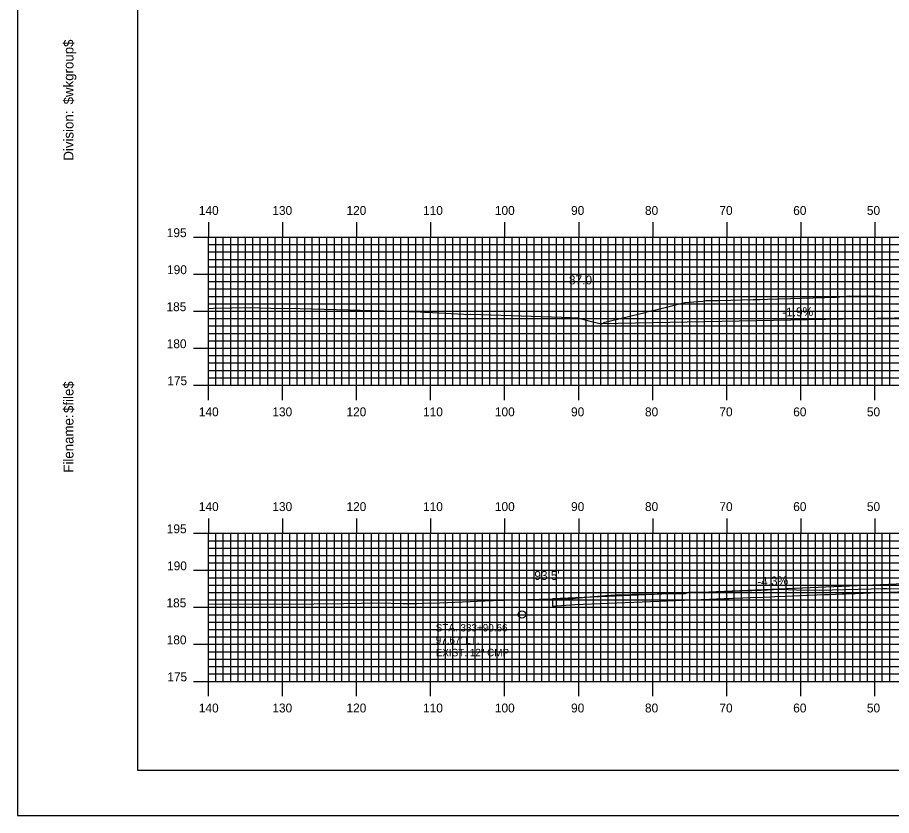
# Model space of a CAD drawing. Extents: x 1823179 to 1823522, y 442591 to 442811.
# Drawn here: x 1823179 to 1823297, y 442590.5 to 442698.3 of the extents above; entities that cross this region are included whole.
import ezdxf

# ---------------------------------------------------------------- set-up
doc = ezdxf.new("R2010")
doc.units = 0
for name, color, linetype in [('ANNOTATION', 7, 'Continuous'), ('BORDER', 7, 'Continuous'), ('D_Drainage_Culvert', 7, 'Continuous'), ('D_Roadway_Drive_SubGrade', 7, 'Continuous'), ('D_Roadway_FinishedGrade', 7, 'Continuous'), ('D_Text_Monospaced', 7, 'Continuous'), ('D_Text_Standard', 7, 'Continuous'), ('H_V ANNOTATION', 7, 'Continuous'), ('MAJOR', 7, 'Continuous'), ('MINOR', 7, 'Continuous'), ('PLOT BOUNDARY', 7, 'Continuous'), ('S_Roadway_Centerline', 7, 'Continuous')]:
    doc.layers.add(name, color=color, linetype=linetype)

msp = doc.modelspace()

# ---------------------------------------------------------------- linework, layer by layer
at = {"layer": 'ANNOTATION'}
msp.add_line((1823310.91, 442622.37), (1823251.26, 442619.82), dxfattribs=at)
at = {"layer": 'BORDER'}
msp.add_lwpolyline([(1823195.2, 442596.67), (1823515.2, 442596.67), (1823515.2, 442806.67), (1823195.2, 442806.67)], close=True, dxfattribs=at)
at = {"layer": 'D_Drainage_Culvert'}
msp.add_circle((1823247.14, 442617.69), 0.5, dxfattribs=at)
at = {"layer": 'D_Roadway_Drive_SubGrade'}
msp.add_line((1823251.26, 442619.82), (1823251.26, 442618.81), dxfattribs=at)
msp.add_lwpolyline([(1823251.26, 442618.81), (1823254.29, 442619.05), (1823272.47, 442619.77), (1823274.43, 442619.84), (1823275.07, 442619.87), (1823275.67, 442619.89), (1823276.97, 442619.94), (1823278, 442619.98), (1823279.69, 442620.05), (1823280.76, 442620.09), (1823281.27, 442620.11), (1823282.72, 442620.17), (1823285.62, 442620.29), (1823285.82, 442620.29), (1823287.99, 442620.38), (1823288.64, 442620.41), (1823290.43, 442620.48), (1823290.86, 442620.49), (1823291.95, 442620.54), (1823292.18, 442620.55), (1823295.24, 442620.67), (1823295.7, 442620.69), (1823295.87, 442620.69), (1823295.89, 442620.69), (1823298.93, 442620.81)], dxfattribs=at)
at = {"layer": 'D_Roadway_FinishedGrade'}
msp.add_line((1823310.62, 442657.95), (1823257.79, 442656.97), dxfattribs=at)
at = {"layer": 'MAJOR'}
for p, q in [((1823204.8, 442670.67), (1823204.8, 442668.67)), ((1823214.8, 442670.67), (1823214.8, 442668.67)), ((1823224.8, 442670.67), (1823224.8, 442668.67)), ((1823234.8, 442670.67), (1823234.8, 442668.67)), ((1823244.8, 442670.67), (1823244.8, 442668.67)), ((1823254.8, 442670.67), (1823254.8, 442668.67)), ((1823264.8, 442670.67), (1823264.8, 442668.67)), ((1823274.8, 442670.67), (1823274.8, 442668.67)), ((1823284.8, 442670.67), (1823284.8, 442668.67)), ((1823294.8, 442670.67), (1823294.8, 442668.67)), ((1823202.79, 442668.67), (1823204.8, 442668.67)), ((1823204.8, 442668.67), (1823484.8, 442668.67)), ((1823204.8, 442648.67), (1823204.8, 442668.67)), ((1823204.8, 442648.67), (1823204.8, 442668.67)), ((1823204.8, 442668.67), (1823484.8, 442668.67)), ((1823214.8, 442648.67), (1823214.8, 442668.67)), ((1823224.8, 442648.67), (1823224.8, 442668.67)), ((1823234.8, 442648.67), (1823234.8, 442668.67)), ((1823244.8, 442648.67), (1823244.8, 442668.67)), ((1823254.8, 442648.67), (1823254.8, 442668.67)), ((1823264.8, 442648.67), (1823264.8, 442668.67)), ((1823274.8, 442648.67), (1823274.8, 442668.67)), ((1823284.8, 442648.67), (1823284.8, 442668.67)), ((1823294.8, 442648.67), (1823294.8, 442668.67)), ((1823202.79, 442663.67), (1823204.8, 442663.67)), ((1823204.8, 442663.67), (1823484.8, 442663.67)), ((1823202.79, 442658.67), (1823204.8, 442658.67)), ((1823204.8, 442658.67), (1823484.8, 442658.67)), ((1823202.79, 442653.67), (1823204.8, 442653.67)), ((1823204.8, 442653.67), (1823484.8, 442653.67)), ((1823202.79, 442648.67), (1823204.8, 442648.67)), ((1823204.8, 442648.67), (1823484.8, 442648.67)), ((1823204.8, 442648.67), (1823484.8, 442648.67)), ((1823204.8, 442646.66), (1823204.8, 442648.67)), ((1823214.8, 442646.66), (1823214.8, 442648.67)), ((1823224.8, 442646.66), (1823224.8, 442648.67)), ((1823234.8, 442646.66), (1823234.8, 442648.67)), ((1823244.8, 442646.66), (1823244.8, 442648.67)), ((1823254.8, 442646.66), (1823254.8, 442648.67)), ((1823264.8, 442646.66), (1823264.8, 442648.67)), ((1823274.8, 442646.66), (1823274.8, 442648.67)), ((1823284.8, 442646.66), (1823284.8, 442648.67)), ((1823294.8, 442646.66), (1823294.8, 442648.67)), ((1823204.8, 442630.67), (1823204.8, 442628.67)), ((1823214.8, 442630.67), (1823214.8, 442628.67)), ((1823224.8, 442630.67), (1823224.8, 442628.67)), ((1823234.8, 442630.67), (1823234.8, 442628.67)), ((1823244.8, 442630.67), (1823244.8, 442628.67)), ((1823254.8, 442630.67), (1823254.8, 442628.67)), ((1823264.8, 442630.67), (1823264.8, 442628.67)), ((1823274.8, 442630.67), (1823274.8, 442628.67)), ((1823284.8, 442630.67), (1823284.8, 442628.67)), ((1823294.8, 442630.67), (1823294.8, 442628.67)), ((1823202.79, 442628.67), (1823204.8, 442628.67)), ((1823204.8, 442628.67), (1823484.8, 442628.67)), ((1823204.8, 442608.67), (1823204.8, 442628.67)), ((1823204.8, 442608.67), (1823204.8, 442628.67)), ((1823204.8, 442628.67), (1823484.8, 442628.67)), ((1823214.8, 442608.67), (1823214.8, 442628.67)), ((1823224.8, 442608.67), (1823224.8, 442628.67)), ((1823234.8, 442608.67), (1823234.8, 442628.67)), ((1823244.8, 442608.67), (1823244.8, 442628.67)), ((1823254.8, 442608.67), (1823254.8, 442628.67)), ((1823264.8, 442608.67), (1823264.8, 442628.67)), ((1823274.8, 442608.67), (1823274.8, 442628.67)), ((1823284.8, 442608.67), (1823284.8, 442628.67)), ((1823294.8, 442608.67), (1823294.8, 442628.67)), ((1823202.79, 442623.67), (1823204.8, 442623.67)), ((1823204.8, 442623.67), (1823484.8, 442623.67)), ((1823202.79, 442618.67), (1823204.8, 442618.67)), ((1823204.8, 442618.67), (1823484.8, 442618.67)), ((1823202.79, 442613.67), (1823204.8, 442613.67)), ((1823204.8, 442613.67), (1823484.8, 442613.67)), ((1823202.79, 442608.67), (1823204.8, 442608.67)), ((1823204.8, 442608.67), (1823484.8, 442608.67)), ((1823204.8, 442608.67), (1823484.8, 442608.67)), ((1823204.8, 442606.66), (1823204.8, 442608.67)), ((1823214.8, 442606.66), (1823214.8, 442608.67)), ((1823224.8, 442606.66), (1823224.8, 442608.67)), ((1823234.8, 442606.66), (1823234.8, 442608.67)), ((1823244.8, 442606.66), (1823244.8, 442608.67)), ((1823254.8, 442606.66), (1823254.8, 442608.67)), ((1823264.8, 442606.66), (1823264.8, 442608.67)), ((1823274.8, 442606.66), (1823274.8, 442608.67)), ((1823284.8, 442606.66), (1823284.8, 442608.67)), ((1823294.8, 442606.66), (1823294.8, 442608.67))]:
    msp.add_line(p, q, dxfattribs=at)
at = {"layer": 'MINOR'}
for p, q in [((1823205.8, 442648.67), (1823205.8, 442668.67)), ((1823206.8, 442648.67), (1823206.8, 442668.67)), ((1823207.8, 442648.67), (1823207.8, 442668.67)), ((1823208.8, 442648.67), (1823208.8, 442668.67)), ((1823209.8, 442648.67), (1823209.8, 442668.67)), ((1823210.8, 442648.67), (1823210.8, 442668.67)), ((1823211.8, 442648.67), (1823211.8, 442668.67)), ((1823212.8, 442648.67), (1823212.8, 442668.67)), ((1823213.8, 442648.67), (1823213.8, 442668.67)), ((1823215.8, 442648.67), (1823215.8, 442668.67)), ((1823216.8, 442648.67), (1823216.8, 442668.67)), ((1823217.8, 442648.67), (1823217.8, 442668.67)), ((1823218.8, 442648.67), (1823218.8, 442668.67)), ((1823219.8, 442648.67), (1823219.8, 442668.67)), ((1823220.8, 442648.67), (1823220.8, 442668.67)), ((1823221.8, 442648.67), (1823221.8, 442668.67)), ((1823222.8, 442648.67), (1823222.8, 442668.67)), ((1823223.8, 442648.67), (1823223.8, 442668.67)), ((1823225.8, 442648.67), (1823225.8, 442668.67)), ((1823226.8, 442648.67), (1823226.8, 442668.67)), ((1823227.8, 442648.67), (1823227.8, 442668.67)), ((1823228.8, 442648.67), (1823228.8, 442668.67)), ((1823229.8, 442648.67), (1823229.8, 442668.67)), ((1823230.8, 442648.67), (1823230.8, 442668.67)), ((1823231.8, 442648.67), (1823231.8, 442668.67)), ((1823232.8, 442648.67), (1823232.8, 442668.67)), ((1823233.8, 442648.67), (1823233.8, 442668.67)), ((1823235.8, 442648.67), (1823235.8, 442668.67)), ((1823236.8, 442648.67), (1823236.8, 442668.67)), ((1823237.8, 442648.67), (1823237.8, 442668.67)), ((1823238.8, 442648.67), (1823238.8, 442668.67)), ((1823239.8, 442648.67), (1823239.8, 442668.67)), ((1823240.8, 442648.67), (1823240.8, 442668.67)), ((1823241.8, 442648.67), (1823241.8, 442668.67)), ((1823242.8, 442648.67), (1823242.8, 442668.67)), ((1823243.8, 442648.67), (1823243.8, 442668.67)), ((1823245.8, 442648.67), (1823245.8, 442668.67)), ((1823246.8, 442648.67), (1823246.8, 442668.67)), ((1823247.8, 442648.67), (1823247.8, 442668.67)), ((1823248.8, 442648.67), (1823248.8, 442668.67)), ((1823249.8, 442648.67), (1823249.8, 442668.67)), ((1823250.8, 442648.67), (1823250.8, 442668.67)), ((1823251.8, 442648.67), (1823251.8, 442668.67)), ((1823252.8, 442648.67), (1823252.8, 442668.67)), ((1823253.8, 442648.67), (1823253.8, 442668.67)), ((1823255.8, 442648.67), (1823255.8, 442668.67)), ((1823256.8, 442648.67), (1823256.8, 442668.67)), ((1823257.8, 442648.67), (1823257.8, 442668.67)), ((1823258.8, 442648.67), (1823258.8, 442668.67)), ((1823259.8, 442648.67), (1823259.8, 442668.67)), ((1823260.8, 442648.67), (1823260.8, 442668.67)), ((1823261.8, 442648.67), (1823261.8, 442668.67)), ((1823262.8, 442648.67), (1823262.8, 442668.67)), ((1823263.8, 442648.67), (1823263.8, 442668.67)), ((1823265.8, 442648.67), (1823265.8, 442668.67)), ((1823266.8, 442648.67), (1823266.8, 442668.67)), ((1823267.8, 442648.67), (1823267.8, 442668.67)), ((1823268.8, 442648.67), (1823268.8, 442668.67)), ((1823269.8, 442648.67), (1823269.8, 442668.67)), ((1823270.8, 442648.67), (1823270.8, 442668.67)), ((1823271.8, 442648.67), (1823271.8, 442668.67)), ((1823272.8, 442648.67), (1823272.8, 442668.67)), ((1823273.8, 442648.67), (1823273.8, 442668.67)), ((1823275.8, 442648.67), (1823275.8, 442668.67)), ((1823276.8, 442648.67), (1823276.8, 442668.67)), ((1823277.8, 442648.67), (1823277.8, 442668.67)), ((1823278.8, 442648.67), (1823278.8, 442668.67)), ((1823279.8, 442648.67), (1823279.8, 442668.67)), ((1823280.8, 442648.67), (1823280.8, 442668.67)), ((1823281.8, 442648.67), (1823281.8, 442668.67)), ((1823282.8, 442648.67), (1823282.8, 442668.67)), ((1823283.8, 442648.67), (1823283.8, 442668.67)), ((1823285.8, 442648.67), (1823285.8, 442668.67)), ((1823286.8, 442648.67), (1823286.8, 442668.67)), ((1823287.8, 442648.67), (1823287.8, 442668.67)), ((1823288.8, 442648.67), (1823288.8, 442668.67)), ((1823289.8, 442648.67), (1823289.8, 442668.67)), ((1823290.8, 442648.67), (1823290.8, 442668.67)), ((1823291.8, 442648.67), (1823291.8, 442668.67)), ((1823292.8, 442648.67), (1823292.8, 442668.67)), ((1823293.8, 442648.67), (1823293.8, 442668.67)), ((1823295.8, 442648.67), (1823295.8, 442668.67)), ((1823296.8, 442648.67), (1823296.8, 442668.67)), ((1823204.8, 442667.67), (1823484.8, 442667.67)), ((1823204.8, 442667.67), (1823206.8, 442667.67)), ((1823204.8, 442666.67), (1823484.8, 442666.67)), ((1823204.8, 442666.67), (1823206.8, 442666.67)), ((1823204.8, 442665.67), (1823484.8, 442665.67)), ((1823204.8, 442665.67), (1823206.8, 442665.67)), ((1823204.8, 442664.67), (1823484.8, 442664.67)), ((1823204.8, 442664.67), (1823206.8, 442664.67)), ((1823204.8, 442662.67), (1823484.8, 442662.67)), ((1823204.8, 442662.67), (1823206.8, 442662.67)), ((1823204.8, 442661.67), (1823484.8, 442661.67)), ((1823204.8, 442661.67), (1823206.8, 442661.67)), ((1823204.8, 442660.67), (1823484.8, 442660.67)), ((1823204.8, 442660.67), (1823206.8, 442660.67)), ((1823204.8, 442659.67), (1823484.8, 442659.67)), ((1823204.8, 442659.67), (1823206.8, 442659.67)), ((1823204.8, 442657.67), (1823484.8, 442657.67)), ((1823204.8, 442657.67), (1823206.8, 442657.67)), ((1823204.8, 442656.67), (1823484.8, 442656.67)), ((1823204.8, 442656.67), (1823206.8, 442656.67)), ((1823204.8, 442655.67), (1823484.8, 442655.67)), ((1823204.8, 442655.67), (1823206.8, 442655.67)), ((1823204.8, 442654.67), (1823484.8, 442654.67)), ((1823204.8, 442654.67), (1823206.8, 442654.67)), ((1823204.8, 442652.67), (1823484.8, 442652.67)), ((1823204.8, 442652.67), (1823206.8, 442652.67)), ((1823204.8, 442651.67), (1823484.8, 442651.67)), ((1823204.8, 442651.67), (1823206.8, 442651.67)), ((1823204.8, 442650.67), (1823484.8, 442650.67)), ((1823204.8, 442650.67), (1823206.8, 442650.67)), ((1823204.8, 442649.67), (1823484.8, 442649.67)), ((1823204.8, 442649.67), (1823206.8, 442649.67)), ((1823205.8, 442608.67), (1823205.8, 442628.67)), ((1823206.8, 442608.67), (1823206.8, 442628.67)), ((1823207.8, 442608.67), (1823207.8, 442628.67)), ((1823208.8, 442608.67), (1823208.8, 442628.67)), ((1823209.8, 442608.67), (1823209.8, 442628.67)), ((1823210.8, 442608.67), (1823210.8, 442628.67)), ((1823211.8, 442608.67), (1823211.8, 442628.67)), ((1823212.8, 442608.67), (1823212.8, 442628.67)), ((1823213.8, 442608.67), (1823213.8, 442628.67)), ((1823215.8, 442608.67), (1823215.8, 442628.67)), ((1823216.8, 442608.67), (1823216.8, 442628.67)), ((1823217.8, 442608.67), (1823217.8, 442628.67)), ((1823218.8, 442608.67), (1823218.8, 442628.67)), ((1823219.8, 442608.67), (1823219.8, 442628.67)), ((1823220.8, 442608.67), (1823220.8, 442628.67)), ((1823221.8, 442608.67), (1823221.8, 442628.67)), ((1823222.8, 442608.67), (1823222.8, 442628.67)), ((1823223.8, 442608.67), (1823223.8, 442628.67)), ((1823225.8, 442608.67), (1823225.8, 442628.67)), ((1823226.8, 442608.67), (1823226.8, 442628.67)), ((1823227.8, 442608.67), (1823227.8, 442628.67)), ((1823228.8, 442608.67), (1823228.8, 442628.67)), ((1823229.8, 442608.67), (1823229.8, 442628.67)), ((1823230.8, 442608.67), (1823230.8, 442628.67)), ((1823231.8, 442608.67), (1823231.8, 442628.67)), ((1823232.8, 442608.67), (1823232.8, 442628.67)), ((1823233.8, 442608.67), (1823233.8, 442628.67)), ((1823235.8, 442608.67), (1823235.8, 442628.67)), ((1823236.8, 442608.67), (1823236.8, 442628.67)), ((1823237.8, 442608.67), (1823237.8, 442628.67)), ((1823238.8, 442608.67), (1823238.8, 442628.67)), ((1823239.8, 442608.67), (1823239.8, 442628.67)), ((1823240.8, 442608.67), (1823240.8, 442628.67)), ((1823241.8, 442608.67), (1823241.8, 442628.67)), ((1823242.8, 442608.67), (1823242.8, 442628.67)), ((1823243.8, 442608.67), (1823243.8, 442628.67)), ((1823245.8, 442608.67), (1823245.8, 442628.67)), ((1823246.8, 442608.67), (1823246.8, 442628.67)), ((1823247.8, 442608.67), (1823247.8, 442628.67)), ((1823248.8, 442608.67), (1823248.8, 442628.67)), ((1823249.8, 442608.67), (1823249.8, 442628.67)), ((1823250.8, 442608.67), (1823250.8, 442628.67)), ((1823251.8, 442608.67), (1823251.8, 442628.67)), ((1823252.8, 442608.67), (1823252.8, 442628.67)), ((1823253.8, 442608.67), (1823253.8, 442628.67)), ((1823255.8, 442608.67), (1823255.8, 442628.67)), ((1823256.8, 442608.67), (1823256.8, 442628.67)), ((1823257.8, 442608.67), (1823257.8, 442628.67)), ((1823258.8, 442608.67), (1823258.8, 442628.67)), ((1823259.8, 442608.67), (1823259.8, 442628.67)), ((1823260.8, 442608.67), (1823260.8, 442628.67)), ((1823261.8, 442608.67), (1823261.8, 442628.67)), ((1823262.8, 442608.67), (1823262.8, 442628.67)), ((1823263.8, 442608.67), (1823263.8, 442628.67)), ((1823265.8, 442608.67), (1823265.8, 442628.67)), ((1823266.8, 442608.67), (1823266.8, 442628.67)), ((1823267.8, 442608.67), (1823267.8, 442628.67)), ((1823268.8, 442608.67), (1823268.8, 442628.67)), ((1823269.8, 442608.67), (1823269.8, 442628.67)), ((1823270.8, 442608.67), (1823270.8, 442628.67)), ((1823271.8, 442608.67), (1823271.8, 442628.67)), ((1823272.8, 442608.67), (1823272.8, 442628.67)), ((1823273.8, 442608.67), (1823273.8, 442628.67)), ((1823275.8, 442608.67), (1823275.8, 442628.67)), ((1823276.8, 442608.67), (1823276.8, 442628.67)), ((1823277.8, 442608.67), (1823277.8, 442628.67)), ((1823278.8, 442608.67), (1823278.8, 442628.67)), ((1823279.8, 442608.67), (1823279.8, 442628.67)), ((1823280.8, 442608.67), (1823280.8, 442628.67)), ((1823281.8, 442608.67), (1823281.8, 442628.67)), ((1823282.8, 442608.67), (1823282.8, 442628.67)), ((1823283.8, 442608.67), (1823283.8, 442628.67)), ((1823285.8, 442608.67), (1823285.8, 442628.67)), ((1823286.8, 442608.67), (1823286.8, 442628.67)), ((1823287.8, 442608.67), (1823287.8, 442628.67)), ((1823288.8, 442608.67), (1823288.8, 442628.67)), ((1823289.8, 442608.67), (1823289.8, 442628.67)), ((1823290.8, 442608.67), (1823290.8, 442628.67)), ((1823291.8, 442608.67), (1823291.8, 442628.67)), ((1823292.8, 442608.67), (1823292.8, 442628.67)), ((1823293.8, 442608.67), (1823293.8, 442628.67)), ((1823295.8, 442608.67), (1823295.8, 442628.67)), ((1823296.8, 442608.67), (1823296.8, 442628.67)), ((1823204.8, 442627.67), (1823484.8, 442627.67)), ((1823204.8, 442627.67), (1823206.8, 442627.67)), ((1823204.8, 442626.67), (1823484.8, 442626.67)), ((1823204.8, 442626.67), (1823206.8, 442626.67)), ((1823204.8, 442625.67), (1823484.8, 442625.67)), ((1823204.8, 442625.67), (1823206.8, 442625.67)), ((1823204.8, 442624.67), (1823484.8, 442624.67)), ((1823204.8, 442624.67), (1823206.8, 442624.67)), ((1823204.8, 442622.67), (1823484.8, 442622.67)), ((1823204.8, 442622.67), (1823206.8, 442622.67)), ((1823204.8, 442621.67), (1823484.8, 442621.67)), ((1823204.8, 442621.67), (1823206.8, 442621.67)), ((1823204.8, 442620.67), (1823484.8, 442620.67)), ((1823204.8, 442620.67), (1823206.8, 442620.67)), ((1823204.8, 442619.67), (1823484.8, 442619.67)), ((1823204.8, 442619.67), (1823206.8, 442619.67)), ((1823204.8, 442617.67), (1823484.8, 442617.67)), ((1823204.8, 442617.67), (1823206.8, 442617.67)), ((1823204.8, 442616.67), (1823484.8, 442616.67)), ((1823204.8, 442616.67), (1823206.8, 442616.67)), ((1823204.8, 442615.67), (1823484.8, 442615.67)), ((1823204.8, 442615.67), (1823206.8, 442615.67)), ((1823204.8, 442614.67), (1823484.8, 442614.67)), ((1823204.8, 442614.67), (1823206.8, 442614.67)), ((1823204.8, 442612.67), (1823484.8, 442612.67)), ((1823204.8, 442612.67), (1823206.8, 442612.67)), ((1823204.8, 442611.67), (1823484.8, 442611.67)), ((1823204.8, 442611.67), (1823206.8, 442611.67)), ((1823204.8, 442610.67), (1823484.8, 442610.67)), ((1823204.8, 442610.67), (1823206.8, 442610.67)), ((1823204.8, 442609.67), (1823484.8, 442609.67)), ((1823204.8, 442609.67), (1823206.8, 442609.67))]:
    msp.add_line(p, q, dxfattribs=at)
at = {"layer": 'PLOT BOUNDARY'}
msp.add_lwpolyline([(1823179.01, 442590.55), (1823519.01, 442590.55), (1823519.01, 442810.55), (1823179.01, 442810.55)], close=True, dxfattribs=at)
at = {"layer": 'S_Roadway_Centerline'}
for points in [[(1823204.8, 442659.05), (1823205.46, 442659.06), (1823210.42, 442659.16), (1823213.24, 442659.08), (1823217.17, 442659.03), (1823233.4, 442658.56), (1823233.96, 442658.55), (1823234.06, 442658.54), (1823234.19, 442658.53), (1823240.15, 442658.21), (1823240.23, 442658.25), (1823253.83, 442657.81), (1823254.67, 442657.76), (1823254.67, 442657.77), (1823256.16, 442657.37), (1823257.64, 442656.99), (1823257.93, 442656.94), (1823258.31, 442657.17), (1823263.78, 442658.51), (1823263.87, 442658.52), (1823264.32, 442658.65), (1823265.02, 442658.8), (1823269.14, 442659.85), (1823271.58, 442660.03), (1823271.97, 442660.09), (1823273.86, 442660.13), (1823278.34, 442660.23), (1823279.31, 442660.25), (1823279.32, 442660.24), (1823280.3, 442660.28), (1823289.57, 442660.56), (1823291.41, 442660.73), (1823295.42, 442660.7), (1823298.3, 442660.6)], [(1823204.8, 442619.12), (1823215.03, 442619.09), (1823223.1, 442619.17), (1823227.84, 442619.26), (1823231.03, 442619.17), (1823232.94, 442619.2), (1823233.84, 442619.22), (1823236.04, 442619.28), (1823242.16, 442619.53), (1823243.27, 442619.61), (1823249.47, 442619.78), (1823253.04, 442619.86), (1823254.06, 442619.88), (1823254.74, 442619.93), (1823254.84, 442619.94), (1823258.43, 442620.28), (1823259.83, 442620.34), (1823261.83, 442620.42), (1823262.04, 442620.44), (1823262.31, 442620.44), (1823268.52, 442620.52), (1823269.21, 442620.54), (1823269.66, 442620.7), (1823273.07, 442620.74), (1823279.45, 442620.97), (1823281.98, 442621.14), (1823284.22, 442621.01), (1823287.28, 442621), (1823294.32, 442621.17), (1823295.72, 442621.2), (1823296.02, 442621.19), (1823296.41, 442621.19), (1823303.07, 442621.03)]]:
    msp.add_lwpolyline(points, dxfattribs=at)

# ---------------------------------------------------------------- texts
at = {"layer": 'ANNOTATION'}
for s, rotation, p in [('-1.9%', 1.0968, (1823282.28, 442657.94)), ('-4.3%', 2.4457, (1823278.92, 442621.53))]:
    msp.add_text(s, height=1.2, rotation=rotation, dxfattribs=at).set_placement(p)
at = {"layer": 'BORDER'}
for s, p in [('$wkgroup$', (1823186.57, 442686.6)), ('Division:', (1823186.57, 442679)), ('$file$', (1823186.57, 442644.92)), ('Filename:', (1823186.57, 442636.86))]:
    msp.add_text(s, height=1.339, rotation=90, dxfattribs=at).set_placement(p)
at = {"layer": 'D_Text_Monospaced'}
for s, p in [('STA. 333+90.66', (1823235.49, 442615.41)), ("97.67' LT.", (1823235.49, 442613.74)), ('EXIST. 12" CMP', (1823235.49, 442612.06))]:
    msp.add_text(s, height=1, dxfattribs=at).set_placement(p)
at = {"layer": 'D_Text_Standard'}
for s, p in [("87.0'", (1823253.48, 442662.29)), ("93.5'", (1823248.81, 442622.37))]:
    msp.add_text(s, height=1.2, dxfattribs=at).set_placement(p)
at = {"layer": 'H_V ANNOTATION'}
for s, p in [('140', (1823203.5, 442671.67)), ('130', (1823213.43, 442671.67)), ('120', (1823223.44, 442671.67)), ('110', (1823233.78, 442671.67)), ('100', (1823243.48, 442671.67)), ('90', (1823253.77, 442671.67)), ('80', (1823263.75, 442671.67)), ('70', (1823273.8, 442671.67)), ('60', (1823283.77, 442671.67)), ('50', (1823293.72, 442671.67)), ('195', (1823199.17, 442668.67)), ('190', (1823199.21, 442663.67)), ('185', (1823199.13, 442658.67)), ('180', (1823199.16, 442653.67)), ('175', (1823199.24, 442648.67)), ('140', (1823203.5, 442644.47)), ('130', (1823213.43, 442644.47)), ('120', (1823223.44, 442644.47)), ('110', (1823233.78, 442644.47)), ('100', (1823243.48, 442644.47)), ('90', (1823253.77, 442644.47)), ('80', (1823263.75, 442644.47)), ('70', (1823273.8, 442644.47)), ('60', (1823283.77, 442644.47)), ('50', (1823293.72, 442644.47)), ('140', (1823203.5, 442631.67)), ('130', (1823213.43, 442631.67)), ('120', (1823223.44, 442631.67)), ('110', (1823233.78, 442631.67)), ('100', (1823243.48, 442631.67)), ('90', (1823253.77, 442631.67)), ('80', (1823263.75, 442631.67)), ('70', (1823273.8, 442631.67)), ('60', (1823283.77, 442631.67)), ('50', (1823293.72, 442631.67)), ('195', (1823199.17, 442628.67)), ('190', (1823199.21, 442623.67)), ('185', (1823199.13, 442618.67)), ('180', (1823199.16, 442613.67)), ('175', (1823199.24, 442608.67)), ('140', (1823203.5, 442604.47)), ('130', (1823213.43, 442604.47)), ('120', (1823223.44, 442604.47)), ('110', (1823233.78, 442604.47)), ('100', (1823243.48, 442604.47)), ('90', (1823253.77, 442604.47)), ('80', (1823263.75, 442604.47)), ('70', (1823273.8, 442604.47)), ('60', (1823283.77, 442604.47)), ('50', (1823293.72, 442604.47))]:
    msp.add_text(s, height=1.2, dxfattribs=at).set_placement(p)
at = {"layer": 'MAJOR'}
for p in [(1823204.79, 442648.67), (1823204.79, 442608.67)]:
    msp.add_text('-', height=0.012, dxfattribs=at).set_placement(p)
at = {"layer": 'S_Roadway_Centerline'}
for s, p in [('C', (1823291.41, 442660.73)), ('L', (1823291.41, 442660.72)), ('C', (1823281.98, 442621.14)), ('L', (1823281.97, 442621.13))]:
    msp.add_text(s, height=0.0146, dxfattribs=at).set_placement(p)

doc.saveas('drawing.dxf')
